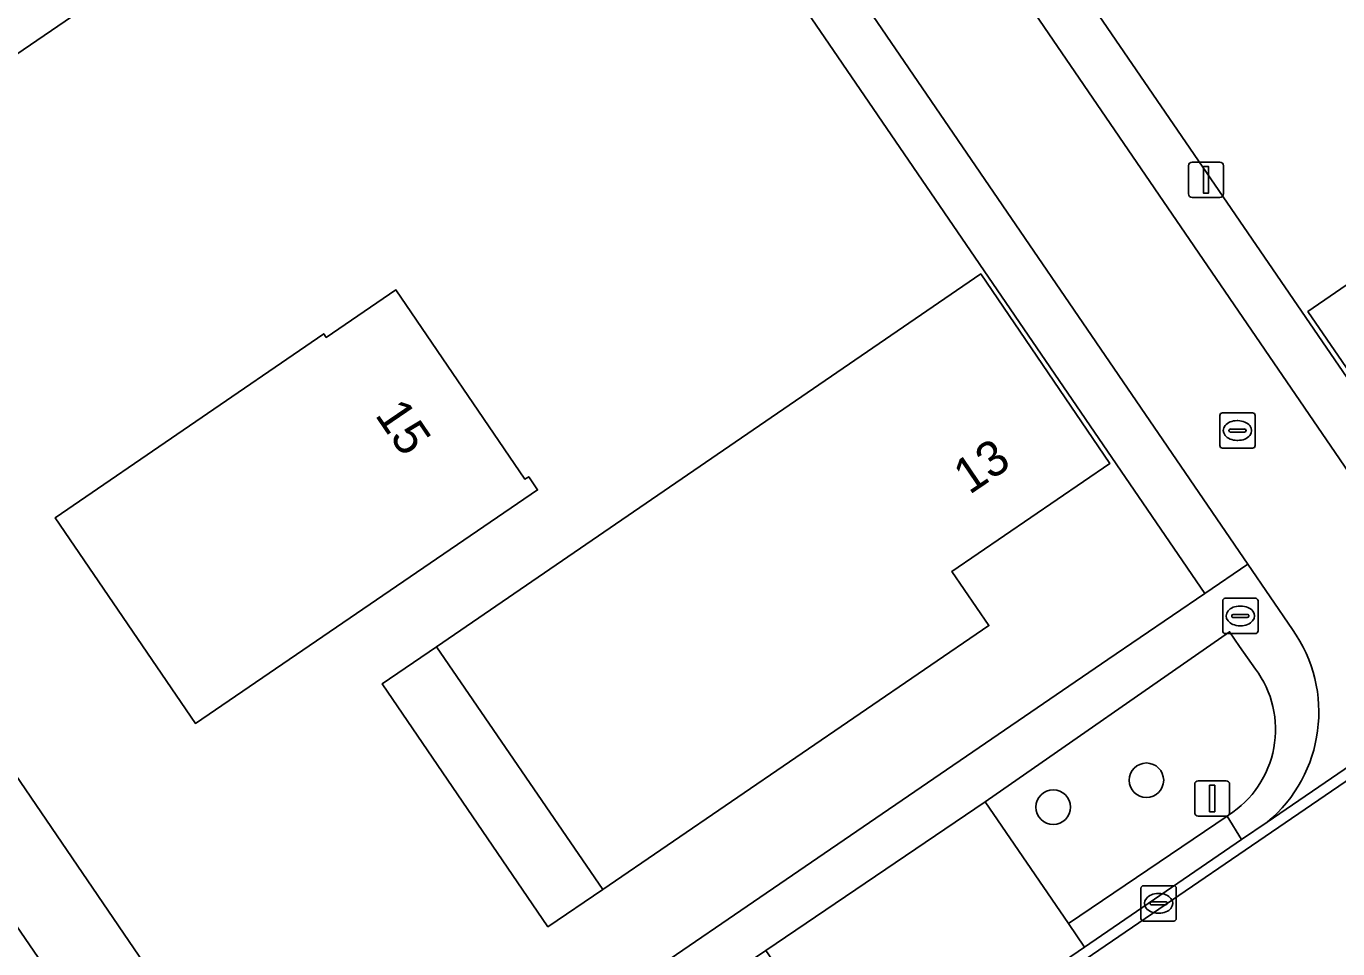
# Model space of a CAD drawing. Extents: x 155275 to 156265, y 382654 to 383635.
# Drawn here: x 155646.86 to 155684.01, y 383328.84 to 383354.97 of the extents above; entities that cross this region are included whole.
import ezdxf

# ---------------------------------------------------------------- set-up
doc = ezdxf.new("R2010")
doc.units = 0
for name, color, linetype in [('IMGEO_Boom', 7, 'Continuous'), ('IMGEO_Brandkraan', 7, 'Continuous'), ('IMGEO_Erf', 7, 'Continuous'), ('IMGEO_Groenvoorziening', 7, 'Continuous'), ('IMGEO_Haag', 7, 'Continuous'), ('IMGEO_Kolk', 7, 'Continuous'), ('IMGEO_Lichtmast', 7, 'Continuous'), ('IMGEO_Pand', 7, 'Continuous'), ('IMGEO_Pand_nummerreeks', 7, 'Continuous'), ('IMGEO_Pand_overbouw', 7, 'Continuous'), ('IMGEO_Parkeervlak_open', 7, 'Continuous'), ('IMGEO_Rijbaan_lokaal_gesloten', 7, 'Continuous'), ('IMGEO_Rijbaan_lokaal_open', 7, 'Continuous'), ('IMGEO_Voetpad_open', 7, 'Continuous')]:
    doc.layers.add(name, color=color, linetype=linetype)

msp = doc.modelspace()

# ---------------------------------------------------------------- linework, layer by layer
at = {"layer": 'IMGEO_Boom'}
for centre in [(155678.591, 383333.617), (155675.951, 383332.856)]:
    msp.add_circle(centre, 0.489, dxfattribs=at)
at = {"layer": 'IMGEO_Brandkraan'}
for p, q in [((155680.826, 383338.771), (155681.678, 383338.771)), ((155680.751, 383337.845), (155680.751, 383338.697)), ((155681.239, 383338.551), (155681.264, 383338.551)), ((155681.752, 383338.697), (155681.752, 383337.845)), ((155681.01, 383338.265), (155681.01, 383338.277)), ((155681.448, 383338.228), (155681.05, 383338.228)), ((155681.053, 383338.314), (155681.451, 383338.314)), ((155681.262, 383337.991), (155681.237, 383337.991)), ((155681.494, 383338.277), (155681.494, 383338.265)), ((155681.678, 383337.771), (155680.826, 383337.771))]:
    msp.add_line(p, q, dxfattribs=at)
for points in [[(155680.826, 383338.771), (155681.678, 383338.771)], [(155680.751, 383337.845), (155680.751, 383338.697)], [(155681.752, 383338.697), (155681.752, 383337.845)], [(155681.678, 383337.771), (155680.826, 383337.771)]]:
    msp.add_lwpolyline(points, dxfattribs=at)
for centre, radius, start, end in [((155680.828, 383338.695), 0.0765, 91.552, 178.448), ((155680.828, 383338.695), 0.0765, 91.552, 178.448), ((155681.676, 383338.695), 0.0765, 1.552, 88.448), ((155681.676, 383338.695), 0.0765, 1.552, 88.448), ((155681.05, 383338.274), 0.0403, 85.8775, 175.7526), ((155681.047, 383338.264), 0.0366, 178.938, 274.7102), ((155681.451, 383338.271), 0.043, 264.8664, 352.4533), ((155681.455, 383338.276), 0.0386, 1.7309, 96.639), ((155680.828, 383337.847), 0.0765, 181.552, 268.448), ((155680.828, 383337.847), 0.0765, 181.552, 268.448), ((155681.676, 383337.847), 0.0765, 271.552, 358.448), ((155681.676, 383337.847), 0.0765, 271.552, 358.448)]:
    msp.add_arc(centre, radius, start, end, dxfattribs=at)
for centre, major_axis, ratio, start_param, end_param in [((155681.238, 383338.271), (-0.387, 0.002), 0.722429, 4.712389, 7.853982), ((155681.263, 383338.271), (-0.39, 0.002), 0.717154, 1.570796, 4.712389)]:
    msp.add_ellipse(centre, major_axis=major_axis, ratio=ratio, start_param=start_param, end_param=end_param, dxfattribs=at)
at = {"layer": 'IMGEO_Erf'}
for points in [[(155657.299, 383431.777), (155657.022, 383432.185), (155634.905, 383417.186), (155657.35, 383384.321), (155685.798, 383342.799), (155707.917, 383357.778), (155706.87, 383359.32)], [(155626.344, 383411.364), (155605.932, 383397.438), (155603.987, 383396.057), (155605.754, 383393.471), (155605.827, 383393.52), (155653.992, 383322.86), (155654.882, 383321.57), (155677.497, 383337.038), (155680.25, 383338.906), (155654.839, 383376.063), (155629.299, 383413.395)], [(155647.303, 383361.927), (155647.013, 383362.352), (155649.769, 383364.231), (155650.055, 383363.812), (155658.911, 383369.873), (155659.212, 383369.426), (155662.297, 383364.905), (155645.369, 383353.349), (155644.717, 383354.302), (155643.781, 383353.657), (155643.882, 383353.509), (155641.508, 383351.891), (155638.669, 383356.028), (155637.151, 383358.24), (155637.284, 383358.325), (155636.638, 383359.304), (155639.894, 383361.521), (155641.364, 383360.503), (155643.288, 383359.179)], [(155688.953, 383350.864), (155691.436, 383347.249), (155685.648, 383343.273), (155683.165, 383346.888)], [(155673.897, 383347.956), (155677.556, 383342.588), (155673.083, 383339.532), (155674.129, 383337.997), (155663.19, 383330.526), (155658.479, 383337.4)], [(155655.286, 383346.262), (155655.356, 383346.159), (155657.332, 383347.504), (155660.985, 383342.139), (155661.092, 383342.212), (155661.346, 383341.84), (155651.652, 383335.225), (155647.678, 383341.048)]]:
    msp.add_lwpolyline(points, close=True, dxfattribs=at)
at = {"layer": 'IMGEO_Groenvoorziening'}
for points in [[(155655.279, 383316.791), (155616.345, 383373.664)], [(155680.948, 383337.822), (155674.021, 383333.004), (155676.383, 383329.556), (155680.874, 383332.601), (155680.919, 383332.631)], [(155681.68, 383336.767), (155681.23, 383337.407), (155680.948, 383337.822)]]:
    msp.add_lwpolyline(points, dxfattribs=at)
msp.add_arc((155679.378, 383335.053), 2.87, 302.4693, 36.6797, dxfattribs=at)
at = {"layer": 'IMGEO_Haag'}
msp.add_lwpolyline([(155655.279, 383316.791), (155616.345, 383373.664)], dxfattribs=at)
at = {"layer": 'IMGEO_Kolk'}
for p, q in [((155680.669, 383343.095), (155680.669, 383343.947)), ((155680.744, 383344.021), (155681.596, 383344.021)), ((155681.67, 383343.947), (155681.67, 383343.095)), ((155680.971, 383343.564), (155681.369, 383343.564)), ((155681.157, 383343.801), (155681.182, 383343.801)), ((155680.928, 383343.515), (155680.928, 383343.527)), ((155681.366, 383343.478), (155680.968, 383343.478)), ((155681.18, 383343.241), (155681.155, 383343.241)), ((155681.412, 383343.527), (155681.412, 383343.515)), ((155681.596, 383343.021), (155680.744, 383343.021)), ((155678.436, 383329.704), (155678.436, 383330.556)), ((155678.511, 383330.63), (155679.363, 383330.63)), ((155679.437, 383330.556), (155679.437, 383329.704)), ((155678.924, 383330.41), (155678.949, 383330.41)), ((155678.695, 383330.124), (155678.695, 383330.136)), ((155679.133, 383330.087), (155678.735, 383330.087)), ((155678.738, 383330.173), (155679.136, 383330.173)), ((155678.947, 383329.85), (155678.922, 383329.85)), ((155679.179, 383330.136), (155679.179, 383330.124)), ((155679.363, 383329.63), (155678.511, 383329.63))]:
    msp.add_line(p, q, dxfattribs=at)
for points in [[(155680.669, 383343.095), (155680.669, 383343.947)], [(155680.744, 383344.021), (155681.596, 383344.021)], [(155681.67, 383343.947), (155681.67, 383343.095)], [(155681.596, 383343.021), (155680.744, 383343.021)], [(155678.436, 383329.704), (155678.436, 383330.556)], [(155678.511, 383330.63), (155679.363, 383330.63)], [(155679.437, 383330.556), (155679.437, 383329.704)], [(155679.363, 383329.63), (155678.511, 383329.63)]]:
    msp.add_lwpolyline(points, dxfattribs=at)
for centre, radius, start, end in [((155680.746, 383343.945), 0.0765, 91.552, 178.448), ((155680.746, 383343.945), 0.0765, 91.552, 178.448), ((155681.594, 383343.945), 0.0765, 1.552, 88.448), ((155681.594, 383343.945), 0.0765, 1.552, 88.448), ((155680.968, 383343.524), 0.0403, 85.8775, 175.7526), ((155681.373, 383343.526), 0.0386, 1.7309, 96.639), ((155680.965, 383343.514), 0.0366, 178.938, 274.7102), ((155681.369, 383343.521), 0.043, 264.8664, 352.4533), ((155680.746, 383343.097), 0.0765, 181.552, 268.448), ((155680.746, 383343.097), 0.0765, 181.552, 268.448), ((155681.594, 383343.097), 0.0765, 271.552, 358.448), ((155681.594, 383343.097), 0.0765, 271.552, 358.448), ((155678.513, 383330.554), 0.0765, 91.552, 178.448), ((155678.513, 383330.554), 0.0765, 91.552, 178.448), ((155679.361, 383330.554), 0.0765, 1.552, 88.448), ((155679.361, 383330.554), 0.0765, 1.552, 88.448), ((155678.735, 383330.133), 0.0403, 85.8775, 175.7526), ((155678.732, 383330.123), 0.0366, 178.938, 274.7102), ((155679.136, 383330.13), 0.043, 264.8664, 352.4533), ((155679.14, 383330.135), 0.0386, 1.7309, 96.639), ((155678.513, 383329.706), 0.0765, 181.552, 268.448), ((155678.513, 383329.706), 0.0765, 181.552, 268.448), ((155679.361, 383329.706), 0.0765, 271.552, 358.448), ((155679.361, 383329.706), 0.0765, 271.552, 358.448)]:
    msp.add_arc(centre, radius, start, end, dxfattribs=at)
for centre, major_axis, ratio, start_param, end_param in [((155681.156, 383343.521), (-0.387, 0.002), 0.722429, 4.712389, 7.853982), ((155681.181, 383343.521), (-0.39, 0.002), 0.717154, 1.570796, 4.712389), ((155678.923, 383330.13), (-0.387, 0.002), 0.722429, 4.712389, 7.853982), ((155678.948, 383330.13), (-0.39, 0.002), 0.717154, 1.570796, 4.712389)]:
    msp.add_ellipse(centre, major_axis=major_axis, ratio=ratio, start_param=start_param, end_param=end_param, dxfattribs=at)
at = {"layer": 'IMGEO_Lichtmast'}
for p, q in [((155679.784, 383350.221), (155679.784, 383351.021)), ((155679.784, 383351.021), (155679.784, 383350.221)), ((155679.884, 383351.121), (155680.674, 383351.121)), ((155680.674, 383351.121), (155679.884, 383351.121)), ((155680.774, 383351.021), (155680.774, 383350.221)), ((155680.774, 383350.221), (155680.774, 383351.021)), ((155680.674, 383350.121), (155679.884, 383350.121)), ((155679.884, 383350.121), (155680.674, 383350.121)), ((155680.059, 383333.601), (155680.849, 383333.601)), ((155680.849, 383333.601), (155680.059, 383333.601)), ((155679.959, 383332.701), (155679.959, 383333.501)), ((155679.959, 383333.501), (155679.959, 383332.701)), ((155680.949, 383333.501), (155680.949, 383332.701)), ((155680.949, 383332.701), (155680.949, 383333.501)), ((155680.849, 383332.601), (155680.059, 383332.601)), ((155680.059, 383332.601), (155680.849, 383332.601))]:
    msp.add_line(p, q, dxfattribs=at)
for points in [[(155680.204, 383350.996), (155680.354, 383350.996), (155680.354, 383350.246), (155680.204, 383350.246), (155680.204, 383350.996)], [(155680.379, 383333.476), (155680.529, 383333.476), (155680.529, 383332.726), (155680.379, 383332.726), (155680.379, 383333.476)]]:
    msp.add_lwpolyline(points, dxfattribs=at)
for centre, start, end in [((155679.884, 383351.021), 90, 180), ((155679.884, 383351.021), 90, 180), ((155680.674, 383351.021), 0, 90), ((155680.674, 383351.021), 360, 90), ((155679.884, 383350.221), 180, 270), ((155679.884, 383350.221), 180, 270), ((155680.674, 383350.221), 270, 0), ((155680.674, 383350.221), 270, 0), ((155680.059, 383333.501), 90, 180), ((155680.059, 383333.501), 90, 180), ((155680.849, 383333.501), 0, 90), ((155680.849, 383333.501), 360, 90), ((155680.059, 383332.701), 180, 270), ((155680.059, 383332.701), 180, 270), ((155680.849, 383332.701), 270, 0), ((155680.849, 383332.701), 270, 0)]:
    msp.add_arc(centre, 0.1, start, end, dxfattribs=at)
at = {"layer": 'IMGEO_Pand'}
for points in [[(155662.297, 383364.905), (155659.212, 383369.426), (155658.911, 383369.873), (155650.055, 383363.812), (155649.769, 383364.231), (155647.013, 383362.352), (155647.303, 383361.927), (155643.288, 383359.179), (155641.364, 383360.503), (155639.894, 383361.521), (155636.638, 383359.304), (155637.284, 383358.325), (155637.151, 383358.24), (155638.669, 383356.028), (155641.508, 383351.891), (155643.882, 383353.509), (155643.781, 383353.657), (155644.717, 383354.302), (155645.369, 383353.349)], [(155685.648, 383343.273), (155691.436, 383347.249), (155688.953, 383350.864), (155683.165, 383346.888)], [(155673.083, 383339.532), (155677.556, 383342.588), (155673.897, 383347.956), (155658.479, 383337.4), (155663.19, 383330.526), (155674.129, 383337.997)], [(155661.346, 383341.84), (155661.092, 383342.212), (155660.985, 383342.139), (155657.332, 383347.504), (155655.356, 383346.159), (155655.286, 383346.262), (155647.678, 383341.048), (155651.652, 383335.225)]]:
    msp.add_lwpolyline(points, close=True, dxfattribs=at)
at = {"layer": 'IMGEO_Pand_overbouw'}
msp.add_lwpolyline([(155658.479, 383337.4), (155656.94, 383336.346), (155661.638, 383329.466), (155663.19, 383330.526)], close=True, dxfattribs=at)
at = {"layer": 'IMGEO_Parkeervlak_open'}
msp.add_lwpolyline([(155676.837, 383328.892), (155676.383, 383329.556), (155674.021, 383333.004), (155667.807, 383328.798), (155670.212, 383325.323), (155670.662, 383324.672)], close=True, dxfattribs=at)
at = {"layer": 'IMGEO_Rijbaan_lokaal_gesloten'}
msp.add_lwpolyline([(155729.169, 383364.646), (155725.003, 383361.806), (155722.109, 383359.832), (155720.939, 383359.034), (155720.795, 383358.936), (155712.721, 383353.417), (155711.461, 383352.556), (155708.502, 383350.534), (155704.381, 383347.717), (155702.484, 383346.42), (155694.239, 383340.786), (155691.911, 383339.195), (155691.095, 383338.637), (155682.011, 383332.429), (155681.289, 383331.935), (155676.837, 383328.892), (155670.662, 383324.672), (155666.533, 383321.85), (155664.45, 383320.426), (155661.244, 383318.235), (155661.404, 383317.986), (155721.169, 383358.828), (155779.897, 383398.895)], dxfattribs=at)
at = {"layer": 'IMGEO_Rijbaan_lokaal_open'}
for points in [[(155629.214, 383416.139), (155630.534, 383414.209), (155681.461, 383339.737), (155682.726, 383337.887)], [(155685.887, 383340.048), (155684.569, 383341.975), (155633.677, 383416.365)], [(155782.106, 383395.69), (155779.897, 383398.895), (155721.169, 383358.828), (155661.404, 383317.986), (155661.244, 383318.235), (155660.115, 383317.515)], [(155682.011, 383332.429), (155691.095, 383338.637)]]:
    msp.add_lwpolyline(points, dxfattribs=at)
msp.add_arc((155679.43, 383335.543), 4.045, 309.654, 35.4195, dxfattribs=at)
at = {"layer": 'IMGEO_Voetpad_open'}
for points in [[(155634.905, 383417.186), (155633.677, 383416.365), (155684.569, 383341.975), (155685.798, 383342.799), (155657.35, 383384.321)], [(155630.534, 383414.209), (155629.299, 383413.395), (155654.839, 383376.063), (155680.25, 383338.906), (155681.461, 383339.737)], [(155681.289, 383331.935), (155680.874, 383332.601), (155676.383, 383329.556), (155676.837, 383328.892)]]:
    msp.add_lwpolyline(points, close=True, dxfattribs=at)
for points in [[(155605.827, 383393.52), (155605.754, 383393.471), (155603.776, 383392.148), (155616.345, 383373.664), (155655.279, 383316.791)], [(155658.21, 383316.737), (155658.043, 383316.991), (155655.599, 383320.531), (155654.882, 383321.57), (155653.992, 383322.86), (155605.827, 383393.52)], [(155681.461, 383339.737), (155680.25, 383338.906), (155677.497, 383337.038), (155654.882, 383321.57), (155655.599, 383320.531), (155661.575, 383324.608), (155663.683, 383326.018), (155667.807, 383328.798), (155674.021, 383333.004), (155680.948, 383337.822), (155681.23, 383337.407), (155681.68, 383336.767)], [(155682.726, 383337.887), (155681.461, 383339.737)], [(155680.919, 383332.631), (155680.874, 383332.601), (155681.289, 383331.935), (155682.011, 383332.429)]]:
    msp.add_lwpolyline(points, dxfattribs=at)
for centre, radius, start, end in [((155679.43, 383335.543), 4.045, 309.654, 35.4195), ((155679.378, 383335.053), 2.87, 302.4693, 36.6797)]:
    msp.add_arc(centre, radius, start, end, dxfattribs=at)

# ---------------------------------------------------------------- texts
at = {"layer": 'IMGEO_Pand_nummerreeks'}
for s, rotation, p in [('15', 304.2512, (155656.719, 383343.963)), ('13', 34.1426, (155673.576, 383341.689))]:
    msp.add_text(s, height=1, rotation=rotation, dxfattribs=at).set_placement(p)

doc.saveas('drawing.dxf')
